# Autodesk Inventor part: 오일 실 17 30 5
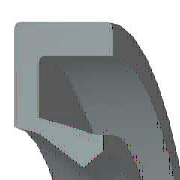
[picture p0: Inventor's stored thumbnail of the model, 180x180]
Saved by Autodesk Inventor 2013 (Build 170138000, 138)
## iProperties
Created: 2012-02
Part Number: 오일 실 17 30 5
Material: 고무
Description: 오일 실 - 스프링 장착, 비스프링, 고무 덮개 G
Document SubType Name: Modeling
Standard: JIS B 2402
Designer: mduedu
Standards Organization: JIS
Language: ko-KR
Size Designation: 17 30 5 A
Categories: <MemberInstance><Categories><Category DisplayName="샤프트 부품" InternalName="7f7aeb1f-a693-4053-b835-cee3144e0d98" Mnemonic="SHFT"><Category DisplayName="실링" Intern
Density: 0.93 g/cm^3
IsCustomPart: 1
Author: mduedu
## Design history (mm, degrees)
fillet "모깎기2" dims "d41" = 0.5
fillet "모깎기3" dims "d42" = 0.5
body "Solid1"
revolve "회전1" stored, may be unused: angle "d29" = 360 deg
fillet "모깎기1" dims "d34" = 0.25 (= 0.05 x b)
sketch "스케치2"
  geometry: L1 (9.58, -3.438)-(9.905, -5); L2 (9.147, -3.282)-(9.58, -3.438); L3 (8.5, -1.72)-(9.147, -3.282); L4 (9.682, -1.22)-(8.5, -1.72); L5 (10.811, -3.75)-(9.682, -1.22); L6 (12.111, -3.75)-(10.811, -3.75); L7 (13.556, -1.25)-(12.111, -3.75); L8 (13.556, 0)-(13.556, -1.25); L9 (15, 0)-(13.556, 0); L10 (15, -5)-(15, 0); L11 (9.905, -5)-(15, -5); L12 (0, -9.6)-(0, 1.6) reference; L13 (28, 0)-(14, 0) reference
  constraints: 22 end point, 3 horizontal, 2 vertical
  dimensions: "d2" = 5 distance of L10.start L9.start (= b); "d4" = 1.25 vertical distance of L5.start L1.end (= 0.25 x b); "d6" = 1.44444 distance of L9.start L8.start (= 0.111111 x dd - 0.111111 x Diam); "d8" = 1.25 distance of L8.start L7.start (= 0.25 x b); "d10" = 1.44444 horizontal distance of L7.start L6.start (= 0.111111 x dd - 0.111111 x Diam); "d12" = 1.21951 vertical distance of L9.start L4.start (= 0.243902 x b); "d14" = 1.18182 horizontal distance of L4.start L3.start (= 0.0909091 x dd - 0.0909091 x Diam); "d16" = 0.5 vertical distance of L4.start L3.start (= 0.1 x b); "d18" = 1.3 distance of L6.start L5.start (= 0.1 x dd - 0.1 x Diam); "d20" = 1.5625 vertical distance of L3.start L2.start (= 0.3125 x b); "d22" = 0.64677 horizontal distance of L3.start L2.start (= 0.0497512 x dd - 0.0497512 x Diam); "d24" = 0.325 horizontal distance of L1.start L1.end (= 0.025 x dd - 0.025 x Diam); "d26" = 1.5625 vertical distance of L1.start L1.end (= 0.3125 x b); "d28" = 0.43333 horizontal distance of L2.start L1.start (= 0.0333333 x dd - 0.0333333 x Diam); "d35" = 0 distance between parallel lines of L13 L9; "d36" = 15 distance between parallel lines of L12 L10 (= 0.5 x dd); "d37" = 8.5 distance from line of L12 L3.start (= 0.5 x Diam)
other parameters: "Diam" = 17 [user parameter; used in 8 equation terms], "b" = 5 [user parameter; used in 8 equation terms], "d1" = 8 (derived), "d3" = 2 (derived), "d5" = 2.22222 (derived), "d7" = 2 (derived), "d9" = 2.22222 (derived), "d11" = 1.95122 (derived), "d13" = 1.81818 (derived), "d15" = 0.8 (derived), "d17" = 2 (derived), "d19" = 2.5 (derived), "d21" = 0.99502 (derived), "d23" = 0.5 (derived), "d25" = 2.5 (derived), "d27" = 0.66667 (derived), "d38" = 0
